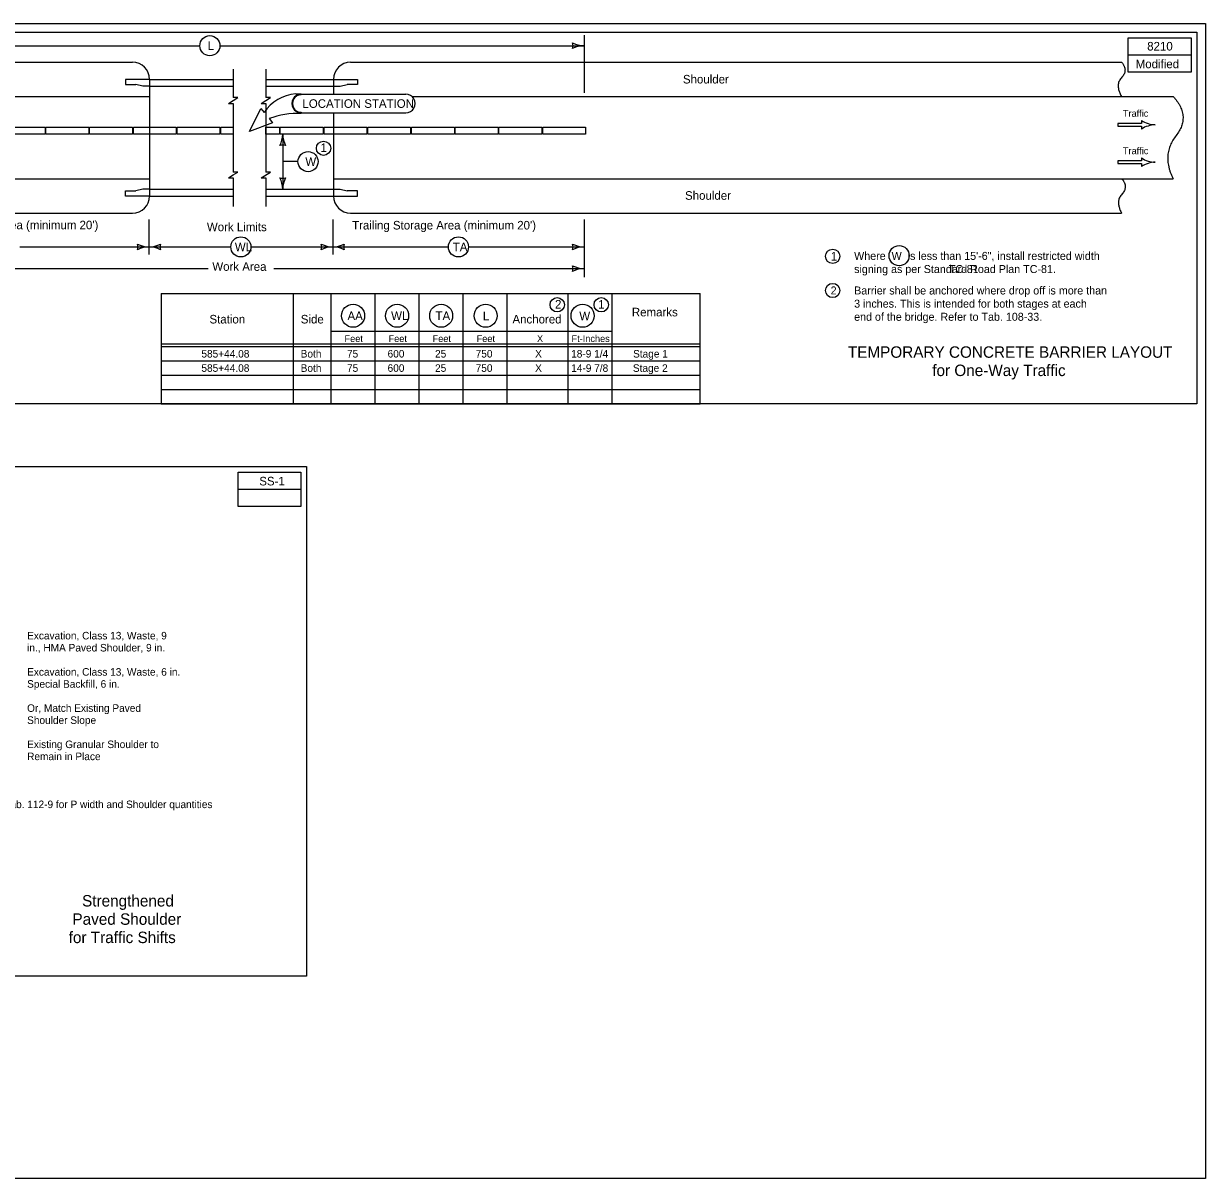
# Model space of a CAD drawing. Extents: x 8045 to 81668, y 6217 to 16762.
# Drawn here: x 14801 to 16868, y 7924 to 9944 of the extents above; entities that cross this region are included whole.
import ezdxf

# ---------------------------------------------------------------- set-up
doc = ezdxf.new("R2010")
doc.units = 0
for name, color, linetype in [('dsnNonPlotable', 7, 'Continuous'), ('dsnShtPlotShapeBatchPrint', 7, 'Continuous'), ('dsnStdBlockModified', 7, 'Continuous'), ('dsnStdBlockNotModified', 7, 'Continuous'), ('dsnStdBorder', 7, 'Continuous'), ('dsnStdLineWork', 7, 'Continuous'), ('dsnStdNameDate', 7, 'Continuous'), ('dsnStdSection', 7, 'Continuous'), ('Level 2', 7, 'Continuous'), ('Level 3', 7, 'Continuous'), ('Level 5', 7, 'Continuous')]:
    doc.layers.add(name, color=color, linetype=linetype)

msp = doc.modelspace()

# ---------------------------------------------------------------- linework, layer by layer
at = {"layer": 'dsnNonPlotable'}
for p, q in [((15781, 9924.1), (15781, 9823.2)), ((14230.5, 9905.4), (15109, 9905.4)), ((15144.3, 9905.4), (15781, 9905.4)), ((13862.8, 9876.4), (14991.3, 9876.4)), ((15167.3, 9864.4), (15167.3, 9814.6)), ((15224.4, 9864.4), (15224.4, 9814.6)), ((15372.7, 9876.4), (16721.1, 9876.4)), ((15021.3, 9846.4), (14979.3, 9846.4)), ((14979.3, 9846.4), (14979.3, 9837.4)), ((14979.3, 9837.4), (14997.3, 9837.4)), ((15009.3, 9834.4), (14997.3, 9837.4)), ((15021.3, 9846.4), (15021.3, 9642.4)), ((15021.3, 9846.4), (15167.3, 9846.4)), ((15224.4, 9846.4), (15342.7, 9846.4)), ((15342.7, 9846.4), (15384.7, 9846.4)), ((15342.7, 9846.4), (15342.7, 9820.5)), ((15354.7, 9834.4), (15366.7, 9837.4)), ((15384.7, 9837.4), (15366.7, 9837.4)), ((15384.7, 9846.4), (15384.7, 9837.4)), ((13779.2, 9816.4), (15021.3, 9816.4)), ((15021.3, 9834.4), (15009.3, 9834.4)), ((15021.3, 9834.4), (15167.3, 9834.4)), ((15224.4, 9834.4), (15342.7, 9834.4)), ((15276.8, 9821), (15286.3, 9821.4)), ((15286.3, 9821.4), (15286.3, 9819.6)), ((15286.3, 9820.5), (15469.4, 9820.5)), ((15342.7, 9834.4), (15354.7, 9834.4)), ((15480.2, 9816.4), (16811.5, 9816.4)), ((15159.3, 9804.5), (15167.3, 9809.5)), ((15159.3, 9804.5), (15167.3, 9804.5)), ((15167.3, 9809.5), (15175.3, 9814.6)), ((15175.3, 9814.6), (15167.3, 9814.6)), ((15167.3, 9804.5), (15167.3, 9744.4)), ((15216.4, 9804.5), (15232.4, 9814.6)), ((15216.4, 9804.5), (15224.4, 9804.5)), ((15232.4, 9814.6), (15224.4, 9814.6)), ((15224.4, 9804.5), (15224.4, 9744.4)), ((15195.9, 9755.5), (15216, 9795.5)), ((15216, 9795.5), (15221.6, 9788.4)), ((15230.2, 9777.8), (15236.1, 9770.5)), ((15286.3, 9788.9), (15286.3, 9787.1)), ((15286.3, 9788), (15469.4, 9788)), ((15342.7, 9788), (15342.7, 9642.4)), ((15236.1, 9770.5), (15195.9, 9755.5)), ((16755.8, 9769.3), (16714.6, 9769.3)), ((16714.6, 9769.3), (16714.6, 9764.8)), ((16714.6, 9764.8), (16755.8, 9764.8)), ((16755.8, 9774.5), (16755.8, 9769.3)), ((16755.8, 9764.8), (16755.8, 9759.5)), ((16779.8, 9767), (16779.8, 9767)), ((15167.3, 9744.4), (15167.3, 9684.4)), ((15224.4, 9744.4), (15224.4, 9684.4)), ((15254, 9750.7), (15254, 9654.4)), ((15280.6, 9702.6), (15254, 9702.6)), ((16755.8, 9703.8), (16714.6, 9703.8)), ((16714.6, 9703.8), (16714.6, 9699.3)), ((16714.6, 9699.3), (16755.8, 9699.3)), ((16755.8, 9709.1), (16755.8, 9703.8)), ((16755.8, 9699.3), (16755.8, 9694.1)), ((16779.8, 9701.6), (16779.8, 9701.6)), ((13779.2, 9672.4), (15021.3, 9672.4)), ((15159.3, 9674.3), (15167.3, 9679.3)), ((15159.3, 9674.3), (15167.3, 9674.3)), ((15167.3, 9679.3), (15175.3, 9684.4)), ((15175.3, 9684.4), (15167.3, 9684.4)), ((15167.3, 9674.3), (15167.3, 9624.4)), ((15216.4, 9674.3), (15232.4, 9684.4)), ((15216.4, 9674.3), (15224.4, 9674.3)), ((15232.4, 9684.4), (15224.4, 9684.4)), ((15224.4, 9674.3), (15224.4, 9624.4)), ((15342.7, 9672.4), (16811.5, 9672.4)), ((14979.3, 9651.4), (14997.3, 9651.4)), ((14979.3, 9642.4), (14979.3, 9651.4)), ((15009.3, 9654.4), (14997.3, 9651.4)), ((15021.3, 9654.4), (15009.3, 9654.4)), ((15021.3, 9654.4), (15167.3, 9654.4)), ((15224.4, 9654.4), (15342.7, 9654.4)), ((15342.7, 9654.4), (15354.7, 9654.4)), ((15354.7, 9654.4), (15366.7, 9651.4)), ((15384.7, 9651.4), (15366.7, 9651.4)), ((15384.7, 9642.4), (15384.7, 9651.4)), ((15021.3, 9642.4), (14979.3, 9642.4)), ((15021.3, 9642.4), (15167.3, 9642.4)), ((15224.4, 9642.4), (15342.7, 9642.4)), ((15342.7, 9642.4), (15384.7, 9642.4)), ((13862.8, 9612.4), (14991.3, 9612.4)), ((15372.7, 9612.4), (16721.1, 9612.4)), ((15020.1, 9601.2), (15020.1, 9539.9)), ((15341.5, 9601.2), (15341.5, 9539.9)), ((15781, 9601.2), (15781, 9500.3)), ((14794, 9553.4), (15020.1, 9553.4)), ((15020.1, 9553.4), (15163.3, 9553.4)), ((15198.3, 9553.4), (15341.5, 9553.4)), ((15211, 9553.4), (15341.5, 9553.4)), ((15341.5, 9553.4), (15543.6, 9553.4)), ((15578.9, 9553.4), (15781, 9553.4)), ((14532.6, 9515.5), (15123.4, 9515.5)), ((15238.7, 9515.5), (15781, 9515.5)), ((15240.1, 9515.5), (15341.5, 9515.5)), ((15272.6, 9279), (15272.6, 9472)), ((15338.6, 9279), (15338.6, 9472)), ((15415.6, 9279), (15415.6, 9472)), ((15492.6, 9279), (15492.6, 9472)), ((15569.6, 9279), (15569.6, 9472)), ((15338.6, 9406.2), (15830.1, 9406.2)), ((15041.6, 9384), (15984.1, 9384)), ((15041.6, 9379), (15984.1, 9379))]:
    msp.add_line(p, q, dxfattribs=at)
for points in [[(14763.3, 9762.7), (14838.3, 9762.7), (14838.3, 9750.7), (14763.3, 9750.7)], [(14839.8, 9762.7), (14914.8, 9762.7), (14914.8, 9750.7), (14839.8, 9750.7)], [(14916.3, 9762.7), (14991.3, 9762.7), (14991.3, 9750.7), (14916.3, 9750.7)], [(14992.8, 9762.7), (15067.8, 9762.7), (15067.8, 9750.7), (14992.8, 9750.7)], [(15069.3, 9762.7), (15144.3, 9762.7), (15144.3, 9750.7), (15069.3, 9750.7)], [(15249.7, 9762.7), (15324.7, 9762.7), (15324.7, 9750.7), (15249.7, 9750.7)], [(15326.2, 9762.7), (15401.2, 9762.7), (15401.2, 9750.7), (15326.2, 9750.7)], [(15402.7, 9762.7), (15477.7, 9762.7), (15477.7, 9750.7), (15402.7, 9750.7)], [(15479.2, 9762.7), (15554.2, 9762.7), (15554.2, 9750.7), (15479.2, 9750.7)], [(15555.7, 9762.7), (15630.7, 9762.7), (15630.7, 9750.7), (15555.7, 9750.7)], [(15632.2, 9762.7), (15707.2, 9762.7), (15707.2, 9750.7), (15632.2, 9750.7)], [(15708.7, 9762.7), (15783.7, 9762.7), (15783.7, 9750.7), (15708.7, 9750.7)]]:
    msp.add_lwpolyline(points, close=True, dxfattribs=at)
for points in [[(15167.3, 9750.7), (15145.8, 9750.7), (15145.8, 9762.7), (15167.3, 9762.7)], [(15167.3, 9762.7), (15167.3, 9750.7)], [(15224.4, 9750.7), (15224.4, 9762.7)], [(15224.4, 9762.7), (15248.2, 9762.7), (15248.2, 9750.7), (15224.4, 9750.7)]]:
    msp.add_lwpolyline(points, dxfattribs=at)
for centre, radius in [((15126.6, 9905.4), 17.6), ((15325.4, 9726), 12.5), ((15298.3, 9702.6), 17.6), ((15180.8, 9553.4), 17.6), ((15561.3, 9553.4), 17.6), ((16215.8, 9537), 12.5), ((16215.8, 9537), 12.5), ((16331.9, 9538.1), 17.6), ((16331.9, 9538.1), 17.6), ((15377.1, 9433), 20.1), ((15454.1, 9433), 20.1), ((15531.1, 9433), 20.1), ((15608.9, 9433), 20.1), ((15734, 9452.2), 12.5), ((15778.4, 9433), 20.1), ((15811, 9452.2), 12.5)]:
    msp.add_circle(centre, radius, dxfattribs=at)
for centre, radius, start, end in [((15745.4, 9905.4), 16.4, 342.2666, 17.7333), ((15781, 9947.9), 42.5, 241.9275, 270), ((15781, 9862.9), 42.5, 90, 118.0725), ((14991.3, 9846.4), 30, 0, 90), ((15372.7, 9846.4), 30, 90, 180), ((16781.7, 9815.4), 48.4, 237.618, 267.648), ((16781.7, 9718.7), 48.4, 92.352, 122.382), ((15211.5, 9750.7), 42.5, 331.9275, 0), ((15296.5, 9750.7), 42.5, 180, 208.0725), ((15254, 9715.1), 16.4, 72.2666, 107.7334), ((16781.7, 9749.9), 48.4, 237.618, 267.648), ((16781.7, 9653.3), 48.4, 92.352, 122.382), ((15254, 9690.1), 16.4, 252.2666, 287.7334), ((15211.5, 9654.4), 42.5, 0, 28.0725), ((15296.5, 9654.4), 42.5, 151.9275, 180), ((14991.3, 9642.4), 30, 270, 360), ((15372.7, 9642.4), 30, 180, 270), ((14984.5, 9553.4), 16.4, 342.2666, 17.7333), ((15020.1, 9595.9), 42.5, 241.9275, 270), ((15020.1, 9510.9), 42.5, 90, 118.0725), ((15020.1, 9595.9), 42.5, 270, 298.0725), ((15020.1, 9510.9), 42.5, 61.9275, 90), ((15055.8, 9553.4), 16.4, 162.2666, 197.7334), ((15305.9, 9553.4), 16.4, 342.2666, 17.7333), ((15341.5, 9595.9), 42.5, 241.9275, 270), ((15341.5, 9510.9), 42.5, 90, 118.0725), ((15341.5, 9595.9), 42.5, 270, 298.0725), ((15341.5, 9510.9), 42.5, 61.9275, 90), ((15377.1, 9553.4), 16.4, 162.2666, 197.7334), ((15745.4, 9553.4), 16.4, 342.2666, 17.7333), ((15781, 9595.9), 42.5, 241.9275, 270), ((15781, 9510.9), 42.5, 90, 118.0725), ((15745.4, 9515.5), 16.4, 342.2666, 17.7333), ((15781, 9558), 42.5, 241.9275, 270), ((15781, 9473), 42.5, 90, 118.0725)]:
    msp.add_arc(centre, radius, start, end, dxfattribs=at)
for centre, major_axis, start_param, end_param in [((15281.3, 9750.7), (-70.8, 0), 4.776871, 5.71778), ((15286.3, 9804.2), (-16.3, 0), 4.712389, 7.853982), ((15286.3, 9804.2), (15.4, 0), 1.570796, 4.712389), ((15469.4, 9804.2), (16.3, 0), 4.712389, 7.853982), ((15283.5, 9631), (-156.9, 0), 4.694293, 5.059134)]:
    msp.add_ellipse(centre, major_axis=major_axis, ratio=0.995025, start_param=start_param, end_param=end_param, dxfattribs=at)
for points in [[(16721.1, 9876.4), (16732.9, 9862.3), (16709.3, 9837.3), (16720.7, 9816.5)], [(16811.5, 9816.4), (16842.9, 9782), (16789.6, 9714), (16811.5, 9672.4)], [(16721.6, 9672.4), (16733.4, 9658.3), (16709.8, 9633.3), (16721.1, 9612.4)]]:
    msp.add_open_spline(points, degree=2, dxfattribs=at)
at = {"layer": 'dsnShtPlotShapeBatchPrint'}
msp.add_lwpolyline([(16842.5, 9919), (16842.5, 9859), (16732.5, 9859), (16732.5, 9919), (16842.5, 9919), (16842.5, 9889), (16732.5, 9889)], dxfattribs=at)
at = {"layer": 'dsnStdBlockModified'}
for p, q in [((13747.5, 9929), (16852.5, 9929)), ((16852.5, 9929), (16852.5, 9279))]:
    msp.add_line(p, q, dxfattribs=at)
at = {"layer": 'dsnStdBlockNotModified'}
for p, q in [((15041.6, 9354), (15984.1, 9354)), ((15041.6, 9329), (15984.1, 9329)), ((15041.6, 9304), (15984.1, 9304)), ((15041.6, 9279), (15984.1, 9279))]:
    msp.add_line(p, q, dxfattribs=at)
at = {"layer": 'dsnStdBorder'}
msp.add_line((16852.5, 9279), (13747.5, 9279), dxfattribs=at)
at = {"layer": 'dsnStdLineWork'}
msp.add_circle((16215.8, 9477.2), 12.5, dxfattribs=at)
at = {"layer": 'dsnStdNameDate'}
msp.add_lwpolyline([(13745, 9169.2), (15295.8, 9169.2), (15295.8, 8277.8), (13745, 8277.8)], close=True, dxfattribs=at)
msp.add_lwpolyline([(15285.8, 9159.2), (15285.8, 9099.2), (15175.8, 9099.2), (15175.8, 9159.2), (15285.8, 9159.2), (15285.8, 9129.2), (15175.8, 9129.2)], dxfattribs=at)
at = {"layer": 'dsnStdSection'}
msp.add_lwpolyline([(13732.5, 9944), (16867.5, 9944), (16867.5, 7924), (13732.5, 7924)], close=True, dxfattribs=at)
at = {"layer": 'Level 2'}
for p, q in [((16852.5, 9929), (16852.5, 9929)), ((15041.6, 9472), (15041.6, 9279)), ((15041.6, 9472), (15984.1, 9472)), ((15646.6, 9279), (15646.6, 9472)), ((15753.1, 9279), (15753.1, 9472)), ((15830.1, 9279), (15830.1, 9472)), ((15984.1, 9279), (15984.1, 9472))]:
    msp.add_line(p, q, dxfattribs=at)

# ---------------------------------------------------------------- texts
at = {"layer": 'dsnStdLineWork'}
for s, height, p in [('2', 14, (16212.2, 9470.2)), ('Barrier shall be anchored where drop off is more than ', 14, (16253.3, 9470.2)), ('3 inches. This is intended for both stages at each ', 14, (16253.3, 9447.2)), ('end of the bridge. Refer to Tab. 108-33.', 14, (16253.3, 9424.2)), ('585+44.08', 13.2, (15111.8, 9359.9)), ('Both', 13.2, (15285.4, 9359.9)), ('75', 13.2, (15366.4, 9359.9)), ('600', 13.2, (15437.4, 9359.9)), ('25', 13.2, (15520.4, 9359.9)), ('750', 13.2, (15591.4, 9359.9)), ('X', 13.2, (15695.4, 9359.9)), ('18-9 1/4', 13.2, (15758.4, 9359.9)), ('Stage 1', 13.2, (15866.7, 9359.9)), ('TEMPORARY CONCRETE BARRIER LAYOUT', 20, (16242.3, 9359.5)), ('585+44.08', 13.2, (15111.8, 9334.9)), ('Both', 13.2, (15285.4, 9334.9)), ('75', 13.2, (15366.4, 9334.9)), ('600', 13.2, (15437.4, 9334.9)), ('25', 13.2, (15520.4, 9334.9)), ('750', 13.2, (15591.4, 9334.9)), ('X', 13.2, (15695.4, 9334.9)), ('14-9 7/8', 13.2, (15758.5, 9334.9)), ('Stage 2', 13.2, (15866.4, 9334.9)), ('for One-Way Traffic', 20, (16389.9, 9327.5)), ('SS-1', 15, (15213, 9136.2)), ('Excavation, Class 13, Waste, 9 ', 13.2, (14807, 8866.8)), ('in., HMA Paved Shoulder, 9 in.', 13.2, (14807, 8845.7)), ('Excavation, Class 13, Waste, 6 in. ', 13.2, (14807, 8803.4)), ('Special Backfill, 6 in.', 13.2, (14807, 8782.3)), ('Or, Match Existing Paved ', 13.2, (14807, 8740.1)), ('Shoulder Slope', 13.2, (14807, 8719)), ('Existing Granular Shoulder to ', 13.2, (14807, 8676.7)), ('Remain in Place', 13.2, (14807, 8655.6)), ('Refer to Tab. 112-9 for P width and Shoulder quantities', 13.2, (14699.4, 8571.7)), ('Strengthened ', 20, (14903.1, 8399.6)), ('Paved Shoulder', 20, (14886.3, 8367.6)), ('for Traffic Shifts', 20, (14879.7, 8335.6))]:
    msp.add_text(s, height=height, dxfattribs=at).set_placement(p)
at = {"layer": 'Level 3'}
for s, p in [('8210', (16765.8, 9897)), ('Modified', (16745.7, 9866))]:
    msp.add_text(s, height=15, dxfattribs=at).set_placement(p)
at = {"layer": 'Level 5'}
for s, height, p in [('L', 15, (15122.7, 9897.9)), ('Shoulder', 15, (15953.9, 9839.3)), ('LOCATION STATION', 15, (15288.5, 9796.7)), ('Traffic', 12, (16723.3, 9781)), ('1', 15, (15320.1, 9719.5)), ('Traffic', 12, (16723.3, 9715.6)), ('W', 15, (15293.6, 9695.1)), ('Shoulder', 15, (15957.6, 9635.9)), ("Approach Storage Area (minimum 20')", 15, (14589.9, 9584.3)), ('Work Limits', 15, (15121.4, 9580.9)), ("Trailing Storage Area (minimum 20')", 15, (15375.4, 9583.9)), ('WL', 15, (15170.3, 9545.9)), ('TA', 15, (15551.4, 9545.9)), ('Work Area', 15, (15130.9, 9511.6)), ('1', 15, (16212.4, 9529.5)), ('1', 15, (16212.4, 9529.5)), ('Where  W  is less than 15\'-6", install restricted width', 14, (16253.3, 9530.7)), ('Where  W  is less than 15\'-6", install restricted width', 14, (16253.3, 9530.7)), ('signing as per Standard Road Plan TC-81.', 14, (16253.3, 9507.7)), ('signing as per Standard Road Plan TC-81.', 14, (16253.3, 9507.7)), ('                                TC-81', 14, (16252.6, 9507.7)), ('                                TC-81', 14, (16252.6, 9507.7)), ('2', 15, (15730.2, 9445.6)), ('1', 15, (15805.8, 9445.6)), ('Remarks', 15, (15864.6, 9431.9)), ('Station', 15, (15125.9, 9419.5)), ('Side', 15, (15285.6, 9419.5)), ('AA', 15, (15367.3, 9425.5)), ('WL', 15, (15443.6, 9425.5)), ('TA', 15, (15521.2, 9425.5)), ('L', 15, (15604, 9425.1)), ('Anchored', 15, (15655.8, 9419.5)), ('W', 15, (15772.7, 9425.1)), ('Feet', 12, (15362.1, 9387)), ('Feet', 12, (15439.1, 9387)), ('Feet', 12, (15516.1, 9387)), ('Feet', 12, (15593.1, 9387)), ('X', 12, (15698.7, 9387)), ('Ft-Inches', 12, (15759.1, 9387))]:
    msp.add_text(s, height=height, dxfattribs=at).set_placement(p)

doc.saveas('drawing.dxf')
